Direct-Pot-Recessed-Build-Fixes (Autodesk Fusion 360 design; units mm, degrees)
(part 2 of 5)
sketch "Spring-side loaded retained M4 nut" plane through (0, 0, 37.9) normal (0, 0, 1) x axis (1, 0, 0)
  line L1 (14.1362, -51.3) -> (16.2724, -55)
  line L2 (9.8638, -51.3) -> (14.1362, -51.3)
  line L3 (7.7276, -55) -> (9.8638, -51.3)
  line L4 (9.8638, -58.7) -> (7.7276, -55)
  line L5 (14.1362, -58.7) -> (9.8638, -58.7)
  line L6 (16.2724, -55) -> (14.1362, -58.7)
extrude "Extrude7" cut sketch "Spring-side loaded retained M4 nut" along normal blind 3.5
work_plane "WorkPlane8" AlongDistance 37.9 ExtraOffset 0
sketch "Spring cup guide bolts" plane through (0, 0, 37.9) normal (0, 0, 1) x axis (1, 0, 0)
  circle C1 centre (5, -55) radius 1.7
extrude "Extrude8" cut sketch "Spring cup guide bolts" along normal blind 14.2
work_plane "WorkPlane9" AlongDistance 37.9 ExtraOffset 0
sketch "Spring cup guide bolts (1)" plane through (0, 0, 37.9) normal (0, 0, 1) x axis (1, 0, 0)
  circle C1 centre (19, -55) radius 1.7
extrude "Extrude9" cut sketch "Spring cup guide bolts (1)" along normal blind 14.2
work_plane "WorkPlane11" AlongDistance -18 ExtraOffset 0
sketch "Dedicated thick stop lug" plane through (-18, 0, 0) normal (1, 0, 0) x axis (0, 0, -1)
  line L1 (-72, 5) -> (-72, -5)
  line L2 (-95, 5) -> (-72, 5)
  line L3 (-95, -5) -> (-95, 5)
  line L4 (-72, -5) -> (-95, -5)
extrude "Extrude11" add sketch "Dedicated thick stop lug" along normal blind 11.5
work_plane "WorkPlane12" AlongDistance -18 ExtraOffset 0
sketch "Rounded stop contact" plane through (-18, 0, 0) normal (1, 0, 0) x axis (0, 0, -1)
  circle C1 centre (-95, 0) radius 5
extrude "Extrude12" add sketch "Rounded stop contact" along normal blind 11.5
work_plane "WorkPlane10" AlongDistance -36 ExtraOffset 0
sketch "Broad stop support ear" plane through (-36, 0, 0) normal (1, 0, 0) x axis (0, 0, -1)
  line L1 (-60, -20) -> (-60, -44)
  line L2 (-90, -20) -> (-60, -20)
  line L3 (-90, -44) -> (-90, -20)
  line L4 (-60, -44) -> (-90, -44)
extrude "Extrude10" add sketch "Broad stop support ear" along normal blind 12
work_plane "WorkPlane11" AlongDistance -24 ExtraOffset 0
sketch "Integrated steel-core end stop" plane through (-24, 0, 0) normal (1, 0, 0) x axis (0, 0, -1)
  circle C1 centre (-79.6754, -33.9652) radius 6
extrude "Extrude11" add sketch "Integrated steel-core end stop" along normal blind 15
work_plane "WorkPlane12" AlongDistance -36.1 ExtraOffset 0
sketch "M5 stop reinforcement bolt" plane through (-36.1, 0, 0) normal (1, 0, 0) x axis (0, 0, -1)
  circle C1 centre (-79.6754, -33.9652) radius 2.7
extrude "Extrude12" cut sketch "M5 stop reinforcement bolt" along normal blind 27.2
work_plane "WorkPlane13" AlongDistance -15.4 ExtraOffset 0
sketch "M5 captive stop nut" plane through (-15.4, 0, 0) normal (1, 0, 0) x axis (0, 0, -1)
  line L1 (-83.8754, -31.5403) -> (-79.6754, -29.1154)
  line L2 (-83.8754, -36.39) -> (-83.8754, -31.5403)
  line L3 (-79.6754, -38.8149) -> (-83.8754, -36.39)
  line L4 (-75.4754, -36.39) -> (-79.6754, -38.8149)
  line L5 (-75.4754, -31.5403) -> (-75.4754, -36.39)
  line L6 (-79.6754, -29.1154) -> (-75.4754, -31.5403)
extrude "Extrude13" cut sketch "M5 captive stop nut" along normal blind 6.5
work_plane "WorkPlane14" AlongDistance -36 ExtraOffset 0
sketch "Broad stop support ear (1)" plane through (-36, 0, 0) normal (1, 0, 0) x axis (0, 0, -1)
  line L1 (-60, 44) -> (-60, 20)
  line L2 (-90, 44) -> (-60, 44)
  line L3 (-90, 20) -> (-90, 44)
  line L4 (-60, 20) -> (-90, 20)
extrude "Extrude14" add sketch "Broad stop support ear (1)" along normal blind 12
work_plane "WorkPlane15" AlongDistance -24 ExtraOffset 0
sketch "Integrated steel-core end stop (1)" plane through (-24, 0, 0) normal (1, 0, 0) x axis (0, 0, -1)
  circle C1 centre (-79.6754, 33.9652) radius 6
extrude "Extrude15" add sketch "Integrated steel-core end stop (1)" along normal blind 15
work_plane "WorkPlane16" AlongDistance -36.1 ExtraOffset 0
sketch "M5 stop reinforcement bolt (1)" plane through (-36.1, 0, 0) normal (1, 0, 0) x axis (0, 0, -1)
  circle C1 centre (-79.6754, 33.9652) radius 2.7
extrude "Extrude16" cut sketch "M5 stop reinforcement bolt (1)" along normal blind 27.2
work_plane "WorkPlane17" AlongDistance -15.4 ExtraOffset 0
sketch "M5 captive stop nut (1)" plane through (-15.4, 0, 0) normal (1, 0, 0) x axis (0, 0, -1)
  line L1 (-83.8754, 36.39) -> (-79.6754, 38.8149)
  line L2 (-83.8754, 31.5403) -> (-83.8754, 36.39)
  line L3 (-79.6754, 29.1154) -> (-83.8754, 31.5403)
  line L4 (-75.4754, 31.5403) -> (-79.6754, 29.1154)
  line L5 (-75.4754, 36.39) -> (-75.4754, 31.5403)
  line L6 (-79.6754, 38.8149) -> (-75.4754, 36.39)
extrude "Extrude17" cut sketch "M5 captive stop nut (1)" along normal blind 6.5
work_plane "WorkPlane13" AlongDistance -24 ExtraOffset 0
sketch "Restore shaft socket through stop-lug root" plane through (-24, 0, 0) normal (1, 0, 0) x axis (0, 0, -1)
  line L1 (-69.6247, 6.65) -> (-60.3753, 6.65)
  arc A1 centre (-65, 0) radius 8.1 clockwise from (-60.3753, 6.65) to (-69.6247, 6.65)
extrude "Extrude13" cut sketch "Restore shaft socket through stop-lug root" along normal blind 48
work_plane "WorkPlane10" AlongDistance -24.1 ExtraOffset 0
sketch "Cam sweep clearance through crossblock" plane through (-24.1, 0, 0) normal (1, 0, 0) x axis (0, 0, -1)
  circle C1 centre (-65, 0) radius 51
extrude "Extrude10" cut sketch "Cam sweep clearance through crossblock" along normal blind 48.2
work_plane "WorkPlane10" AlongDistance 36 ExtraOffset 0
sketch "Rigid sensor carriage support" plane through (36, 0, 0) normal (1, 0, 0) x axis (0, 0, -1)
  line L1 (-49, -18) -> (-49, -28)
  line L2 (-81, -18) -> (-49, -18)
  line L3 (-81, -28) -> (-81, -18)
  line L4 (-49, -28) -> (-81, -28)
extrude "Extrude10" add sketch "Rigid sensor carriage support" along normal blind 44
work_plane "WorkPlane11" AlongDistance -28.1 ExtraOffset 0
sketch "M3 sensor carriage heat set" plane through (0, -28.1, 0) normal (0, 1, 0) x axis (1, 0, 0)
  circle C1 centre (74, -65) radius 2
extrude "Extrude11" cut sketch "M3 sensor carriage heat set" along normal blind 6.8
work_plane "WorkPlane12" AlongDistance 36 ExtraOffset 0
sketch "Rigid sensor carriage support (1)" plane through (36, 0, 0) normal (1, 0, 0) x axis (0, 0, -1)
  line L1 (-49, 28) -> (-49, 18)
  line L2 (-81, 28) -> (-49, 28)
  line L3 (-81, 18) -> (-81, 28)
  line L4 (-49, 18) -> (-81, 18)
extrude "Extrude12" add sketch "Rigid sensor carriage support (1)" along normal blind 44
work_plane "WorkPlane13" AlongDistance 21.3 ExtraOffset 0
sketch "M3 sensor carriage heat set (1)" plane through (0, 21.3, 0) normal (0, 1, 0) x axis (1, 0, 0)
  circle C1 centre (74, -65) radius 2
extrude "Extrude13" cut sketch "M3 sensor carriage heat set (1)" along normal blind 6.8
work_plane "WorkPlane1" AlongDistance -24 ExtraOffset 0
sketch "Controlled follower end float" plane through (-24, 0, 0) normal (1, 0, 0) x axis (0, 0, -1)
  circle C1 centre (-12, -35) radius 6
extrude "Extrude1" new body sketch "Controlled follower end float" along normal blind 27.8 bodies "P21 Follower left axial spacer"
work_plane "WorkPlane2" AlongDistance -24.1 ExtraOffset 0
sketch "Pivot sleeve running clearance" plane through (-24.1, 0, 0) normal (1, 0, 0) x axis (0, 0, -1)
  circle C1 centre (-12, -35) radius 4.2
extrude "Extrude2" cut sketch "Pivot sleeve running clearance" along normal blind 28
work_plane "WorkPlane1" AlongDistance 20.2 ExtraOffset 0
sketch "Controlled follower end float" plane through (20.2, 0, 0) normal (1, 0, 0) x axis (0, 0, -1)
  circle C1 centre (-12, -35) radius 6
extrude "Extrude1" new body sketch "Controlled follower end float" along normal blind 3.8 bodies "P22 Follower right axial spacer"
work_plane "WorkPlane2" AlongDistance 20.1 ExtraOffset 0
sketch "Pivot sleeve running clearance" plane through (20.1, 0, 0) normal (1, 0, 0) x axis (0, 0, -1)
  circle C1 centre (-12, -35) radius 4.2
extrude "Extrude2" cut sketch "Pivot sleeve running clearance" along normal blind 4
work_plane "WorkPlane1" AlongDistance 3.1 ExtraOffset 0
sketch "Roller axle M3 nut" plane through (3.1, 0, 0) normal (1, 0, 0) x axis (0, 0, -1)
  line L1 (-14.75, 1.5877) -> (-12, 3.1754)
  line L2 (-14.75, -1.5877) -> (-14.75, 1.5877)
  line L3 (-12, -3.1754) -> (-14.75, -1.5877)
  line L4 (-9.25, -1.5877) -> (-12, -3.1754)
  line L5 (-9.25, 1.5877) -> (-9.25, -1.5877)
  line L6 (-12, 3.1754) -> (-9.25, 1.5877)
extrude "Extrude1" new body sketch "Roller axle M3 nut" along normal blind 2.4 bodies "HARDWARE Roller axle M3 nut"
work_plane "WorkPlane2" AlongDistance 3 ExtraOffset 0
sketch "Thread envelope" plane through (3, 0, 0) normal (1, 0, 0) x axis (0, 0, -1)
  circle C1 centre (-12, 0) radius 1.5
extrude "Extrude2" cut sketch "Thread envelope" along normal blind 2.6
work_plane "WorkPlane14" AlongDistance 23.9 ExtraOffset 0
sketch "Cam lateral service opening" plane through (23.9, 0, 0) normal (1, 0, 0) x axis (0, 0, -1)
  line L1 (-42.2047, 46.7373) -> (-43.8497, 47.5044)
  line L2 (-40.5875, 45.9133) -> (-42.2047, 46.7373)
  line L3 (-39, 45.0333) -> (-40.5875, 45.9133)
  line L4 (-37.4442, 44.0985) -> (-39, 45.0333)
  line L5 (-35.922, 43.11) -> (-37.4442, 44.0985)
  line L6 (-34.4352, 42.0689) -> (-35.922, 43.11)
  line L7 (-32.9856, 40.9766) -> (-34.4352, 42.0689)
  line L8 (-31.575, 39.8343) -> (-32.9856, 40.9766)
  line L9 (-30.2052, 38.6435) -> (-31.575, 39.8343)
  line L10 (-28.8778, 37.4057) -> (-30.2052, 38.6435)
  line L11 (-27.5943, 36.1222) -> (-28.8778, 37.4057)
  line L12 (-26.3565, 34.7948) -> (-27.5943, 36.1222)
  line L13 (-25.1657, 33.425) -> (-26.3565, 34.7948)
  line L14 (-24.0234, 32.0144) -> (-25.1657, 33.425)
  line L15 (-22.9311, 30.5648) -> (-24.0234, 32.0144)
  line L16 (-21.89, 29.078) -> (-22.9311, 30.5648)
  line L17 (-20.9015, 27.5558) -> (-21.89, 29.078)
  line L18 (-19.9667, 26) -> (-20.9015, 27.5558)
  line L19 (-19.0867, 24.4125) -> (-19.9667, 26)
  line L20 (-18.2627, 22.7953) -> (-19.0867, 24.4125)
  line L21 (-17.4956, 21.1503) -> (-18.2627, 22.7953)
  line L22 (-16.7864, 19.4795) -> (-17.4956, 21.1503)
  line L23 (-16.136, 17.785) -> (-16.7864, 19.4795)
  line L24 (-15.5451, 16.0689) -> (-16.136, 17.785)
  line L25 (-15.0144, 14.3331) -> (-15.5451, 16.0689)
  line L26 (-14.5446, 12.5799) -> (-15.0144, 14.3331)
  line L27 (-14.1363, 10.8114) -> (-14.5446, 12.5799)
  line L28 (-13.79, 9.0297) -> (-14.1363, 10.8114)
  line L29 (-13.5061, 7.237) -> (-13.79, 9.0297)
  line L30 (-13.2849, 5.4355) -> (-13.5061, 7.237)
  line L31 (-13.1267, 3.6273) -> (-13.2849, 5.4355)
  line L32 (-13.0317, 1.8148) -> (-13.1267, 3.6273)
  line L33 (-13, 0) -> (-13.0317, 1.8148)
  line L34 (-13.0317, -1.8148) -> (-13, 0)
  line L35 (-13.1267, -3.6273) -> (-13.0317, -1.8148)
  line L36 (-13.2849, -5.4355) -> (-13.1267, -3.6273)
  line L37 (-13.5061, -7.237) -> (-13.2849, -5.4355)
  line L38 (-13.79, -9.0297) -> (-13.5061, -7.237)
  line L39 (-14.1363, -10.8114) -> (-13.79, -9.0297)
  line L40 (-14.5446, -12.5799) -> (-14.1363, -10.8114)
  line L41 (-15.0144, -14.3331) -> (-14.5446, -12.5799)
  line L42 (-15.5451, -16.0689) -> (-15.0144, -14.3331)
  line L43 (-16.136, -17.785) -> (-15.5451, -16.0689)
  line L44 (-16.7864, -19.4795) -> (-16.136, -17.785)
  line L45 (-17.4956, -21.1503) -> (-16.7864, -19.4795)
  line L46 (-18.2627, -22.7953) -> (-17.4956, -21.1503)
  line L47 (-19.0867, -24.4125) -> (-18.2627, -22.7953)
  line L48 (-19.9667, -26) -> (-19.0867, -24.4125)
  line L49 (-20.9015, -27.5558) -> (-19.9667, -26)
  line L50 (-21.89, -29.078) -> (-20.9015, -27.5558)
  line L51 (-22.9311, -30.5648) -> (-21.89, -29.078)
  line L52 (-24.0234, -32.0144) -> (-22.9311, -30.5648)
  line L53 (-25.1657, -33.425) -> (-24.0234, -32.0144)
  line L54 (-26.3565, -34.7948) -> (-25.1657, -33.425)
  line L55 (-27.5943, -36.1222) -> (-26.3565, -34.7948)
  line L56 (-28.8778, -37.4057) -> (-27.5943, -36.1222)
  line L57 (-30.2052, -38.6435) -> (-28.8778, -37.4057)
  line L58 (-31.575, -39.8343) -> (-30.2052, -38.6435)
  line L59 (-32.9856, -40.9766) -> (-31.575, -39.8343)
  line L60 (-34.4352, -42.0689) -> (-32.9856, -40.9766)
  line L61 (-35.922, -43.11) -> (-34.4352, -42.0689)
  line L62 (-37.4442, -44.0985) -> (-35.922, -43.11)
  line L63 (-39, -45.0333) -> (-37.4442, -44.0985)
  line L64 (-40.5875, -45.9133) -> (-39, -45.0333)
  line L65 (-42.2047, -46.7373) -> (-40.5875, -45.9133)
  line L66 (-43.8497, -47.5044) -> (-42.2047, -46.7373)
  line L67 (-54.4248, -23.7522) -> (-43.8497, -47.5044)
  line L68 (-53.6024, -23.3686) -> (-54.4248, -23.7522)
  line L69 (-52.7937, -22.9566) -> (-53.6024, -23.3686)
  line L70 (-52, -22.5167) -> (-52.7937, -22.9566)
  line L71 (-51.2221, -22.0493) -> (-52, -22.5167)
  line L72 (-50.461, -21.555) -> (-51.2221, -22.0493)
  line L73 (-49.7176, -21.0344) -> (-50.461, -21.555)
  line L74 (-48.9928, -20.4883) -> (-49.7176, -21.0344)
  line L75 (-48.2875, -19.9172) -> (-48.9928, -20.4883)
  line L76 (-47.6026, -19.3218) -> (-48.2875, -19.9172)
  line L77 (-46.9389, -18.7028) -> (-47.6026, -19.3218)
  line L78 (-46.2972, -18.0611) -> (-46.9389, -18.7028)
  line L79 (-45.6782, -17.3974) -> (-46.2972, -18.0611)
  line L80 (-45.0828, -16.7125) -> (-45.6782, -17.3974)
  line L81 (-44.5117, -16.0072) -> (-45.0828, -16.7125)
  line L82 (-43.9656, -15.2824) -> (-44.5117, -16.0072)
  line L83 (-43.445, -14.539) -> (-43.9656, -15.2824)
  line L84 (-42.9507, -13.7779) -> (-43.445, -14.539)
  line L85 (-42.4833, -13) -> (-42.9507, -13.7779)
  line L86 (-42.0434, -12.2063) -> (-42.4833, -13)
  line L87 (-41.6314, -11.3976) -> (-42.0434, -12.2063)
  line L88 (-41.2478, -10.5752) -> (-41.6314, -11.3976)
  line L89 (-40.8932, -9.7398) -> (-41.2478, -10.5752)
  line L90 (-40.568, -8.8925) -> (-40.8932, -9.7398)
  line L91 (-40.2725, -8.0344) -> (-40.568, -8.8925)
  line L92 (-40.0072, -7.1666) -> (-40.2725, -8.0344)
  line L93 (-39.7723, -6.29) -> (-40.0072, -7.1666)
  line L94 (-39.5682, -5.4057) -> (-39.7723, -6.29)
  line L95 (-39.395, -4.5149) -> (-39.5682, -5.4057)
  line L96 (-39.253, -3.6185) -> (-39.395, -4.5149)
  line L97 (-39.1424, -2.7177) -> (-39.253, -3.6185)
  line L98 (-39.0633, -1.8137) -> (-39.1424, -2.7177)
  line L99 (-39.0158, -0.9074) -> (-39.0633, -1.8137)
  line L100 (-39, 0) -> (-39.0158, -0.9074)
  line L101 (-39.0158, 0.9074) -> (-39, 0)
  line L102 (-39.0633, 1.8137) -> (-39.0158, 0.9074)
  line L103 (-39.1424, 2.7177) -> (-39.0633, 1.8137)
  line L104 (-39.253, 3.6185) -> (-39.1424, 2.7177)
  line L105 (-39.395, 4.5149) -> (-39.253, 3.6185)
  line L106 (-39.5682, 5.4057) -> (-39.395, 4.5149)
  line L107 (-39.7723, 6.29) -> (-39.5682, 5.4057)
  line L108 (-40.0072, 7.1666) -> (-39.7723, 6.29)
  line L109 (-40.2725, 8.0344) -> (-40.0072, 7.1666)
  line L110 (-40.568, 8.8925) -> (-40.2725, 8.0344)
  line L111 (-40.8932, 9.7398) -> (-40.568, 8.8925)
  line L112 (-41.2478, 10.5752) -> (-40.8932, 9.7398)
  line L113 (-41.6314, 11.3976) -> (-41.2478, 10.5752)
  line L114 (-42.0434, 12.2063) -> (-41.6314, 11.3976)
  line L115 (-42.4833, 13) -> (-42.0434, 12.2063)
  line L116 (-42.9507, 13.7779) -> (-42.4833, 13)
  line L117 (-43.445, 14.539) -> (-42.9507, 13.7779)
  line L118 (-43.9656, 15.2824) -> (-43.445, 14.539)
  line L119 (-44.5117, 16.0072) -> (-43.9656, 15.2824)
  line L120 (-45.0828, 16.7125) -> (-44.5117, 16.0072)
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extrude "Extrude14" cut sketch "Cam lateral service opening" along normal blind 12.2
work_plane "WorkPlane15" AlongDistance 36 ExtraOffset 0
sketch "Clear service path beneath sensor rails" plane through (36, 0, 0) normal (1, 0, 0) x axis (0, 0, -1)
  line L1 (-48.9, -18) -> (-48.9, -28)
  line L2 (-56, -18) -> (-48.9, -18)
  line L3 (-56, -28) -> (-56, -18)
  line L4 (-48.9, -28) -> (-56, -28)
extrude "Extrude15" cut sketch "Clear service path beneath sensor rails" along normal blind 44.1
work_plane "WorkPlane16" AlongDistance 36 ExtraOffset 0
sketch "Clear service path beneath sensor rails (1)" plane through (36, 0, 0) normal (1, 0, 0) x axis (0, 0, -1)
  line L1 (-48.9, 28) -> (-48.9, 18)
  line L2 (-56, 28) -> (-48.9, 28)
  line L3 (-56, 18) -> (-56, 28)
  line L4 (-48.9, 18) -> (-56, 18)
extrude "Extrude16" cut sketch "Clear service path beneath sensor rails (1)" along normal blind 44.1
work_plane "WorkPlane11" AlongDistance -24 ExtraOffset 0
sketch "Raise mount clear of rail bolt axes" plane through (-24, 0, 0) normal (1, 0, 0) x axis (0, 0, -1)
  line L1 (-52, -44) -> (-52, -66)
  line L2 (-57, -44) -> (-52, -44)
  line L3 (-57, -66) -> (-57, -44)
  line L4 (-52, -66) -> (-57, -66)
extrude "Extrude11" add sketch "Raise mount clear of rail bolt axes" along normal blind 48
work_plane "WorkPlane12" AlongDistance -24 ExtraOffset 0
sketch "Close old block mounting hole" plane through (-24, 0, 0) normal (1, 0, 0) x axis (0, 0, -1)
  circle C1 centre (-44, -59) radius 2.01
extrude "Extrude12" add sketch "Close old block mounting hole" along normal blind 8.7
work_plane "WorkPlane13" AlongDistance -24.1 ExtraOffset 0
sketch "Raised M3 block insert" plane through (-24.1, 0, 0) normal (1, 0, 0) x axis (0, 0, -1)
  circle C1 centre (-52, -59) radius 2
extrude "Extrude13" cut sketch "Raised M3 block insert" along normal blind 8.9
work_plane "WorkPlane14" AlongDistance 15.3 ExtraOffset 0
sketch "Close old block mounting hole (1)" plane through (15.3, 0, 0) normal (1, 0, 0) x axis (0, 0, -1)
  circle C1 centre (-44, -59) radius 2.01
extrude "Extrude14" add sketch "Close old block mounting hole (1)" along normal blind 8.7
work_plane "WorkPlane15" AlongDistance 15.2 ExtraOffset 0
sketch "Raised M3 block insert (1)" plane through (15.2, 0, 0) normal (1, 0, 0) x axis (0, 0, -1)
  circle C1 centre (-52, -59) radius 2
extrude "Extrude15" cut sketch "Raised M3 block insert (1)" along normal blind 8.9
work_plane "WorkPlane18" AlongDistance -36 ExtraOffset 0
sketch "Close old plate mounting hole" plane through (-36, 0, 0) normal (1, 0, 0) x axis (0, 0, -1)
  circle C1 centre (-44, -59) radius 1.71
extrude "Extrude18" add sketch "Close old plate mounting hole" along normal blind 12
work_plane "WorkPlane19" AlongDistance -36.1 ExtraOffset 0
sketch "Raised M3 block fastener" plane through (-36.1, 0, 0) normal (1, 0, 0) x axis (0, 0, -1)
  circle C1 centre (-52, -59) radius 1.7
extrude "Extrude19" cut sketch "Raised M3 block fastener" along normal blind 12.2
work_plane "WorkPlane17" AlongDistance 24 ExtraOffset 0
sketch "Close old plate mounting hole" plane through (24, 0, 0) normal (1, 0, 0) x axis (0, 0, -1)
  circle C1 centre (-44, -59) radius 1.71
extrude "Extrude17" add sketch "Close old plate mounting hole" along normal blind 12
work_plane "WorkPlane18" AlongDistance 23.9 ExtraOffset 0
sketch "Raised M3 block fastener" plane through (23.9, 0, 0) normal (1, 0, 0) x axis (0, 0, -1)
  circle C1 centre (-52, -59) radius 1.7
extrude "Extrude18" cut sketch "Raised M3 block fastener" along normal blind 12.2
work_plane "WorkPlane16" AlongDistance -24 ExtraOffset 0
sketch "Close old block mounting hole (2)" plane through (-24, 0, 0) normal (1, 0, 0) x axis (0, 0, -1)
  circle C1 centre (-44, -51) radius 2.01
extrude "Extrude16" add sketch "Close old block mounting hole (2)" along normal blind 8.7
work_plane "WorkPlane17" AlongDistance -24.1 ExtraOffset 0
sketch "Raised M3 block insert (2)" plane through (-24.1, 0, 0) normal (1, 0, 0) x axis (0, 0, -1)
  circle C1 centre (-52, -51) radius 2
extrude "Extrude17" cut sketch "Raised M3 block insert (2)" along normal blind 8.9
work_plane "WorkPlane18" AlongDistance 15.3 ExtraOffset 0
sketch "Close old block mounting hole (3)" plane through (15.3, 0, 0) normal (1, 0, 0) x axis (0, 0, -1)
  circle C1 centre (-44, -51) radius 2.01
extrude "Extrude18" add sketch "Close old block mounting hole (3)" along normal blind 8.7
work_plane "WorkPlane19" AlongDistance 15.2 ExtraOffset 0
sketch "Raised M3 block insert (3)" plane through (15.2, 0, 0) normal (1, 0, 0) x axis (0, 0, -1)
  circle C1 centre (-52, -51) radius 2
extrude "Extrude19" cut sketch "Raised M3 block insert (3)" along normal blind 8.9
work_plane "WorkPlane20" AlongDistance -36 ExtraOffset 0
sketch "Close old plate mounting hole (1)" plane through (-36, 0, 0) normal (1, 0, 0) x axis (0, 0, -1)
  circle C1 centre (-44, -51) radius 1.71
extrude "Extrude20" add sketch "Close old plate mounting hole (1)" along normal blind 12
work_plane "WorkPlane21" AlongDistance -36.1 ExtraOffset 0
sketch "Raised M3 block fastener (1)" plane through (-36.1, 0, 0) normal (1, 0, 0) x axis (0, 0, -1)
  circle C1 centre (-52, -51) radius 1.7
extrude "Extrude21" cut sketch "Raised M3 block fastener (1)" along normal blind 12.2
work_plane "WorkPlane19" AlongDistance 24 ExtraOffset 0
sketch "Close old plate mounting hole (1)" plane through (24, 0, 0) normal (1, 0, 0) x axis (0, 0, -1)
  circle C1 centre (-44, -51) radius 1.71
extrude "Extrude19" add sketch "Close old plate mounting hole (1)" along normal blind 12
work_plane "WorkPlane20" AlongDistance 23.9 ExtraOffset 0
sketch "Raised M3 block fastener (1)" plane through (23.9, 0, 0) normal (1, 0, 0) x axis (0, 0, -1)
  circle C1 centre (-52, -51) radius 1.7
extrude "Extrude20" cut sketch "Raised M3 block fastener (1)" along normal blind 12.2
work_plane "WorkPlane20" AlongDistance 51.9 ExtraOffset 0
sketch "Continue adjuster bore" plane through (0, 0, 51.9) normal (0, 0, 1) x axis (1, 0, 0)
  circle C1 centre (12, -55) radius 2.2
extrude "Extrude20" cut sketch "Continue adjuster bore" along normal blind 5.2
work_plane "WorkPlane21" AlongDistance 51.9 ExtraOffset 0
sketch "Continue guide bore" plane through (0, 0, 51.9) normal (0, 0, 1) x axis (1, 0, 0)
  circle C1 centre (5, -55) radius 1.7
extrude "Extrude21" cut sketch "Continue guide bore" along normal blind 5.2
work_plane "WorkPlane22" AlongDistance 51.9 ExtraOffset 0
sketch "Continue guide bore (1)" plane through (0, 0, 51.9) normal (0, 0, 1) x axis (1, 0, 0)
  circle C1 centre (19, -55) radius 1.7
extrude "Extrude22" cut sketch "Continue guide bore (1)" along normal blind 5.2
work_plane "WorkPlane23" AlongDistance -24.1 ExtraOffset 0
sketch "Preserve cam sweep clearance" plane through (-24.1, 0, 0) normal (1, 0, 0) x axis (0, 0, -1)
  circle C1 centre (-65, 0) radius 51
extrude "Extrude23" cut sketch "Preserve cam sweep clearance" along normal blind 48.2
work_plane "WorkPlane8" AlongDistance 37.25 ExtraOffset 0
sketch "Flat shoulder aligns with shaft print bed" plane through (37.25, 0, 0) normal (1, 0, 0) x axis (0, 0, -1)
  line L1 (-54, 11) -> (-54, 6.5)
  line L2 (-76, 11) -> (-54, 11)
  line L3 (-76, 6.5) -> (-76, 11)
  line L4 (-54, 6.5) -> (-76, 6.5)
extrude "Extrude8" cut sketch "Flat shoulder aligns with shaft print bed" along normal blind 3.2
work_plane "WorkPlane1" AlongDistance -23.85 ExtraOffset 0
sketch "Controlled rotor axial clearance" plane through (-23.85, 0, 0) normal (1, 0, 0) x axis (0, 0, -1)
  circle C1 centre (-65, 0) radius 10
extrude "Extrude1" new body sketch "Controlled rotor axial clearance" along normal blind 16.85 bodies "P23 Left rotor thrust spacer"
work_plane "WorkPlane2" AlongDistance -23.95 ExtraOffset 0
sketch "Free spacer bore" plane through (-23.95, 0, 0) normal (1, 0, 0) x axis (0, 0, -1)
  circle C1 centre (-65, 0) radius 8.2
extrude "Extrude2" cut sketch "Free spacer bore" along normal blind 17.05
work_plane "WorkPlane1" AlongDistance 7 ExtraOffset 0
sketch "Controlled rotor axial clearance" plane through (7, 0, 0) normal (1, 0, 0) x axis (0, 0, -1)
  circle C1 centre (-65, 0) radius 10
extrude "Extrude1" new body sketch "Controlled rotor axial clearance" along normal blind 16.85 bodies "P24 Right rotor thrust spacer"
work_plane "WorkPlane2" AlongDistance 6.9 ExtraOffset 0
sketch "Free spacer bore" plane through (6.9, 0, 0) normal (1, 0, 0) x axis (0, 0, -1)
  circle C1 centre (-65, 0) radius 8.2
extrude "Extrude2" cut sketch "Free spacer bore" along normal blind 17.05
work_plane "WorkPlane22" AlongDistance -76 ExtraOffset 0
sketch "Restore rail bolt clearance after hole filling" plane through (0, -76, 0) normal (0, 1, 0) x axis (1, 0, 0)
  circle C1 centre (-30, -45) radius 2.7
extrude "Extrude22" cut sketch "Restore rail bolt clearance after hole filling" along normal blind 22
work_plane "WorkPlane23" AlongDistance 54 ExtraOffset 0
sketch "Restore rail bolt clearance after hole filling (1)" plane through (0, 54, 0) normal (0, 1, 0) x axis (1, 0, 0)
  circle C1 centre (-30, -45) radius 2.7
work_plane "WorkPlane24" AlongDistance -55 ExtraOffset 0
sketch "Restore rail head access after hole filling" plane through (0, -55, 0) normal (0, 1, 0) x axis (1, 0, 0)
  circle C1 centre (-30, -45) radius 5.3
extrude "Extrude24" cut sketch "Restore rail head access after hole filling" along normal blind 12
work_plane "WorkPlane25" AlongDistance 43 ExtraOffset 0
sketch "Restore rail head access after hole filling (1)" plane through (0, 43, 0) normal (0, 1, 0) x axis (1, 0, 0)
  circle C1 centre (-30, -45) radius 5.3
work_plane "WorkPlane21" AlongDistance -76 ExtraOffset 0
sketch "Restore rail bolt clearance after hole filling" plane through (0, -76, 0) normal (0, 1, 0) x axis (1, 0, 0)
  circle C1 centre (30, -45) radius 2.7
extrude "Extrude21" cut sketch "Restore rail bolt clearance after hole filling" along normal blind 22
work_plane "WorkPlane22" AlongDistance 54 ExtraOffset 0
sketch "Restore rail bolt clearance after hole filling (1)" plane through (0, 54, 0) normal (0, 1, 0) x axis (1, 0, 0)
  circle C1 centre (30, -45) radius 2.7
work_plane "WorkPlane23" AlongDistance -55 ExtraOffset 0
sketch "Restore rail head access after hole filling" plane through (0, -55, 0) normal (0, 1, 0) x axis (1, 0, 0)
  circle C1 centre (30, -45) radius 5.3
extrude "Extrude23" cut sketch "Restore rail head access after hole filling" along normal blind 12
work_plane "WorkPlane24" AlongDistance 43 ExtraOffset 0
sketch "Restore rail head access after hole filling (1)" plane through (0, 43, 0) normal (0, 1, 0) x axis (1, 0, 0)
  circle C1 centre (30, -45) radius 5.3
work_plane "WorkPlane14" AlongDistance -18.1 ExtraOffset 0
sketch "Stop lug clearance for concentric thrust spacer" plane through (-18.1, 0, 0) normal (1, 0, 0) x axis (0, 0, -1)
  circle C1 centre (-65, 0) radius 10.2
extrude "Extrude14" cut sketch "Stop lug clearance for concentric thrust spacer" along normal blind 11
work_plane "WorkPlane15" AlongDistance -18.1 ExtraOffset 0
sketch "Complete stop lug relief to rotor face" plane through (-18.1, 0, 0) normal (1, 0, 0) x axis (0, 0, -1)
  circle C1 centre (-65, 0) radius 10.2
extrude "Extrude15" cut sketch "Complete stop lug relief to rotor face" along normal blind 11.1
ground "Pin2"
ground "Pin3"
ground "Pin4"
ground "Pin5"
ground "Pin6"
ground "Pin11"
ground "Pin12"
ground "Pin48"
ground "Pin49"
work_plane "WorkPlane24" AlongDistance -24 ExtraOffset 0
sketch "Extra roof over relocated heat-set inserts" plane through (-24, 0, 0) normal (1, 0, 0) x axis (0, 0, -1)
  line L1 (-57, -44) -> (-57, -66)
  line L2 (-59, -44) -> (-57, -44)
  line L3 (-59, -66) -> (-59, -44)
  line L4 (-57, -66) -> (-59, -66)
extrude "Extrude24" add sketch "Extra roof over relocated heat-set inserts" along normal blind 48
work_plane "WorkPlane25" AlongDistance -24 ExtraOffset 0
sketch "Fill former insert location" plane through (-24, 0, 0) normal (1, 0, 0) x axis (0, 0, -1)
  circle C1 centre (-52, -59) radius 2.01
extrude "Extrude25" add sketch "Fill former insert location" along normal blind 8.7
work_plane "WorkPlane26" AlongDistance 15.3 ExtraOffset 0
sketch "Fill former insert location (1)" plane through (15.3, 0, 0) normal (1, 0, 0) x axis (0, 0, -1)
  circle C1 centre (-52, -59) radius 2.01
extrude "Extrude26" add sketch "Fill former insert location (1)" along normal blind 8.7
work_plane "WorkPlane26" AlongDistance -36 ExtraOffset 0
sketch "Fill former plate mounting hole" plane through (-36, 0, 0) normal (1, 0, 0) x axis (0, 0, -1)
  circle C1 centre (-52, -59) radius 1.71
extrude "Extrude26" add sketch "Fill former plate mounting hole" along normal blind 12
work_plane "WorkPlane25" AlongDistance 24 ExtraOffset 0
sketch "Fill former plate mounting hole" plane through (24, 0, 0) normal (1, 0, 0) x axis (0, 0, -1)
  circle C1 centre (-52, -59) radius 1.71
extrude "Extrude25" add sketch "Fill former plate mounting hole" along normal blind 12
work_plane "WorkPlane27" AlongDistance -24 ExtraOffset 0
sketch "Fill former insert location (2)" plane through (-24, 0, 0) normal (1, 0, 0) x axis (0, 0, -1)
  circle C1 centre (-52, -51) radius 2.01
extrude "Extrude27" add sketch "Fill former insert location (2)" along normal blind 8.7
work_plane "WorkPlane28" AlongDistance 15.3 ExtraOffset 0
sketch "Fill former insert location (3)" plane through (15.3, 0, 0) normal (1, 0, 0) x axis (0, 0, -1)
  circle C1 centre (-52, -51) radius 2.01
extrude "Extrude28" add sketch "Fill former insert location (3)" along normal blind 8.7
work_plane "WorkPlane27" AlongDistance -36 ExtraOffset 0
sketch "Fill former plate mounting hole (1)" plane through (-36, 0, 0) normal (1, 0, 0) x axis (0, 0, -1)
  circle C1 centre (-52, -51) radius 1.71
extrude "Extrude27" add sketch "Fill former plate mounting hole (1)" along normal blind 12
work_plane "WorkPlane26" AlongDistance 24 ExtraOffset 0
sketch "Fill former plate mounting hole (1)" plane through (24, 0, 0) normal (1, 0, 0) x axis (0, 0, -1)
  circle C1 centre (-52, -51) radius 1.71
extrude "Extrude26" add sketch "Fill former plate mounting hole (1)" along normal blind 12
work_plane "WorkPlane29" AlongDistance -24.1 ExtraOffset 0
sketch "Relocated insert with cam-side retaining wall" plane through (-24.1, 0, 0) normal (1, 0, 0) x axis (0, 0, -1)
  circle C1 centre (-53.5, -62) radius 2
extrude "Extrude29" cut sketch "Relocated insert with cam-side retaining wall" along normal blind 8.9
work_plane "WorkPlane30" AlongDistance 15.3 ExtraOffset 0
sketch "Relocated insert with cam-side retaining wall (1)" plane through (15.3, 0, 0) normal (1, 0, 0) x axis (0, 0, -1)
  circle C1 centre (-53.5, -62) radius 2
extrude "Extrude30" cut sketch "Relocated insert with cam-side retaining wall (1)" along normal blind 8.9
work_plane "WorkPlane28" AlongDistance -36.1 ExtraOffset 0
sketch "Relocated mount above rail counterbore" plane through (-36.1, 0, 0) normal (1, 0, 0) x axis (0, 0, -1)
  circle C1 centre (-53.5, -62) radius 1.7
extrude "Extrude28" cut sketch "Relocated mount above rail counterbore" along normal blind 12.2
work_plane "WorkPlane27" AlongDistance 23.9 ExtraOffset 0
sketch "Relocated mount above rail counterbore" plane through (23.9, 0, 0) normal (1, 0, 0) x axis (0, 0, -1)
  circle C1 centre (-53.5, -62) radius 1.7
extrude "Extrude27" cut sketch "Relocated mount above rail counterbore" along normal blind 12.2
work_plane "WorkPlane31" AlongDistance -24.1 ExtraOffset 0
sketch "Relocated insert with cam-side retaining wall (2)" plane through (-24.1, 0, 0) normal (1, 0, 0) x axis (0, 0, -1)
  circle C1 centre (-53.5, -54) radius 2
extrude "Extrude31" cut sketch "Relocated insert with cam-side retaining wall (2)" along normal blind 8.9
work_plane "WorkPlane32" AlongDistance 15.3 ExtraOffset 0
sketch "Relocated insert with cam-side retaining wall (3)" plane through (15.3, 0, 0) normal (1, 0, 0) x axis (0, 0, -1)
  circle C1 centre (-53.5, -54) radius 2
extrude "Extrude32" cut sketch "Relocated insert with cam-side retaining wall (3)" along normal blind 8.9
work_plane "WorkPlane29" AlongDistance -36.1 ExtraOffset 0
sketch "Relocated mount above rail counterbore (1)" plane through (-36.1, 0, 0) normal (1, 0, 0) x axis (0, 0, -1)
  circle C1 centre (-53.5, -54) radius 1.7
extrude "Extrude29" cut sketch "Relocated mount above rail counterbore (1)" along normal blind 12.2
work_plane "WorkPlane28" AlongDistance 23.9 ExtraOffset 0
sketch "Relocated mount above rail counterbore (1)" plane through (23.9, 0, 0) normal (1, 0, 0) x axis (0, 0, -1)
  circle C1 centre (-53.5, -54) radius 1.7
extrude "Extrude28" cut sketch "Relocated mount above rail counterbore (1)" along normal blind 12.2
work_plane "WorkPlane33" AlongDistance 51.9 ExtraOffset 0
sketch "Continue adjuster bore through roof" plane through (0, 0, 51.9) normal (0, 0, 1) x axis (1, 0, 0)
  circle C1 centre (12, -55) radius 2.2
extrude "Extrude33" cut sketch "Continue adjuster bore through roof" along normal blind 7.2
work_plane "WorkPlane34" AlongDistance 51.9 ExtraOffset 0
sketch "Continue guide bore through roof" plane through (0, 0, 51.9) normal (0, 0, 1) x axis (1, 0, 0)
  circle C1 centre (5, -55) radius 1.7
extrude "Extrude34" cut sketch "Continue guide bore through roof" along normal blind 7.2
work_plane "WorkPlane35" AlongDistance 51.9 ExtraOffset 0
sketch "Continue guide bore through roof (1)" plane through (0, 0, 51.9) normal (0, 0, 1) x axis (1, 0, 0)
  circle C1 centre (19, -55) radius 1.7
extrude "Extrude35" cut sketch "Continue guide bore through roof (1)" along normal blind 7.2
work_plane "WorkPlane36" AlongDistance -24.1 ExtraOffset 0
sketch "Restore cam envelope after pocket repair" plane through (-24.1, 0, 0) normal (1, 0, 0) x axis (0, 0, -1)
  circle C1 centre (-65, 0) radius 51
extrude "Extrude36" cut sketch "Restore cam envelope after pocket repair" along normal blind 48.2
work_plane "WorkPlane30" AlongDistance -76 ExtraOffset 0
sketch "Preserve rail shank passage" plane through (0, -76, 0) normal (0, 1, 0) x axis (1, 0, 0)
  circle C1 centre (-30, -45) radius 2.7
work_plane "WorkPlane31" AlongDistance 54 ExtraOffset 0
sketch "Preserve rail shank passage (1)" plane through (0, 54, 0) normal (0, 1, 0) x axis (1, 0, 0)
  circle C1 centre (-30, -45) radius 2.7
work_plane "WorkPlane32" AlongDistance -55 ExtraOffset 0
sketch "Preserve rail head passage" plane through (0, -55, 0) normal (0, 1, 0) x axis (1, 0, 0)
  circle C1 centre (-30, -45) radius 5.3
extrude "Extrude32" cut sketch "Preserve rail head passage" along normal blind 12
work_plane "WorkPlane33" AlongDistance 43 ExtraOffset 0
sketch "Preserve rail head passage (1)" plane through (0, 43, 0) normal (0, 1, 0) x axis (1, 0, 0)
  circle C1 centre (-30, -45) radius 5.3
work_plane "WorkPlane29" AlongDistance -76 ExtraOffset 0
sketch "Preserve rail shank passage" plane through (0, -76, 0) normal (0, 1, 0) x axis (1, 0, 0)
  circle C1 centre (30, -45) radius 2.7
work_plane "WorkPlane30" AlongDistance 54 ExtraOffset 0
sketch "Preserve rail shank passage (1)" plane through (0, 54, 0) normal (0, 1, 0) x axis (1, 0, 0)
  circle C1 centre (30, -45) radius 2.7
work_plane "WorkPlane31" AlongDistance -55 ExtraOffset 0
sketch "Preserve rail head passage" plane through (0, -55, 0) normal (0, 1, 0) x axis (1, 0, 0)
  circle C1 centre (30, -45) radius 5.3
extrude "Extrude31" cut sketch "Preserve rail head passage" along normal blind 12
work_plane "WorkPlane32" AlongDistance 43 ExtraOffset 0
sketch "Preserve rail head passage (1)" plane through (0, 43, 0) normal (0, 1, 0) x axis (1, 0, 0)
  circle C1 centre (30, -45) radius 5.3
work_plane "WorkPlane16" AlongDistance -5 ExtraOffset 0
sketch "Flat washer seat for sensor-drive shaft clamp" plane through (-5, 0, 0) normal (1, 0, 0) x axis (0, 0, -1)
  line L1 (-60, 22) -> (-60, 20)
  line L2 (-70, 22) -> (-60, 22)
  line L3 (-70, 20) -> (-70, 22)
  line L4 (-60, 20) -> (-70, 20)
extrude "Extrude16" add sketch "Flat washer seat for sensor-drive shaft clamp" along normal blind 10
work_plane "WorkPlane17" AlongDistance 6.4 ExtraOffset 0
sketch "Radial screw onto printed shaft D flat" plane through (0, 6.4, 0) normal (0, 1, 0) x axis (1, 0, 0)
  circle C1 centre (0, -65) radius 1.7
extrude "Extrude17" cut sketch "Radial screw onto printed shaft D flat" along normal blind 15.7
work_plane "WorkPlane18" AlongDistance 15.2 ExtraOffset 0
sketch "M3 heatset pocket for rotor clamp" plane through (0, 15.2, 0) normal (0, 1, 0) x axis (1, 0, 0)
  circle C1 centre (0, -65) radius 2
work_plane "WorkPlane37" AlongDistance -24 ExtraOffset 0
sketch "Extend reaction block into free rail bay" plane through (-24, 0, 0) normal (1, 0, 0) x axis (0, 0, -1)
  line L1 (-38, -66) -> (-38, -74)
  line L2 (-59, -66) -> (-38, -66)
  line L3 (-59, -74) -> (-59, -66)
  line L4 (-38, -74) -> (-59, -74)
extrude "Extrude37" add sketch "Extend reaction block into free rail bay" along normal blind 48
work_plane "WorkPlane38" AlongDistance -24 ExtraOffset 0
sketch "Close mounting bore that crossed cup guide" plane through (-24, 0, 0) normal (1, 0, 0) x axis (0, 0, -1)
  circle C1 centre (-53.5, -54) radius 2.01
extrude "Extrude38" add sketch "Close mounting bore that crossed cup guide" along normal blind 8.7
work_plane "WorkPlane39" AlongDistance -24.1 ExtraOffset 0
sketch "Outer mounting row clear of guide" plane through (-24.1, 0, 0) normal (1, 0, 0) x axis (0, 0, -1)
  circle C1 centre (-53.5, -70) radius 2
extrude "Extrude39" cut sketch "Outer mounting row clear of guide" along normal blind 8.9
work_plane "WorkPlane40" AlongDistance 15.3 ExtraOffset 0
sketch "Close mounting bore that crossed cup guide (1)" plane through (15.3, 0, 0) normal (1, 0, 0) x axis (0, 0, -1)
  circle C1 centre (-53.5, -54) radius 2.01
extrude "Extrude40" add sketch "Close mounting bore that crossed cup guide (1)" along normal blind 8.7
work_plane "WorkPlane41" AlongDistance 15.2 ExtraOffset 0
sketch "Outer mounting row clear of guide (1)" plane through (15.2, 0, 0) normal (1, 0, 0) x axis (0, 0, -1)
  circle C1 centre (-53.5, -70) radius 2
extrude "Extrude41" cut sketch "Outer mounting row clear of guide (1)" along normal blind 8.9
work_plane "WorkPlane34" AlongDistance -36 ExtraOffset 0
sketch "Close former inner mounting hole" plane through (-36, 0, 0) normal (1, 0, 0) x axis (0, 0, -1)
  circle C1 centre (-53.5, -54) radius 1.71
extrude "Extrude34" add sketch "Close former inner mounting hole" along normal blind 12
work_plane "WorkPlane35" AlongDistance -36.1 ExtraOffset 0
sketch "Matched outer mounting row" plane through (-36.1, 0, 0) normal (1, 0, 0) x axis (0, 0, -1)
  circle C1 centre (-53.5, -70) radius 1.7
extrude "Extrude35" cut sketch "Matched outer mounting row" along normal blind 12.2
work_plane "WorkPlane33" AlongDistance 24 ExtraOffset 0
sketch "Close former inner mounting hole" plane through (24, 0, 0) normal (1, 0, 0) x axis (0, 0, -1)
  circle C1 centre (-53.5, -54) radius 1.71
extrude "Extrude33" add sketch "Close former inner mounting hole" along normal blind 12
work_plane "WorkPlane34" AlongDistance 23.9 ExtraOffset 0
sketch "Matched outer mounting row" plane through (23.9, 0, 0) normal (1, 0, 0) x axis (0, 0, -1)
  circle C1 centre (-53.5, -70) radius 1.7
extrude "Extrude34" cut sketch "Matched outer mounting row" along normal blind 12.2
work_plane "WorkPlane42" AlongDistance 37.9 ExtraOffset 0
sketch "Restore separate cup guide bore" plane through (0, 0, 37.9) normal (0, 0, 1) x axis (1, 0, 0)
  circle C1 centre (5, -55) radius 1.7
work_plane "WorkPlane43" AlongDistance 37.9 ExtraOffset 0
sketch "Restore separate cup guide bore (1)" plane through (0, 0, 37.9) normal (0, 0, 1) x axis (1, 0, 0)
  circle C1 centre (19, -55) radius 1.7
extrude "Extrude43" cut sketch "Restore separate cup guide bore (1)" along normal blind 21.2
work_plane "WorkPlane44" AlongDistance -24.1 ExtraOffset 0
sketch "Preserve cam envelope" plane through (-24.1, 0, 0) normal (1, 0, 0) x axis (0, 0, -1)
  circle C1 centre (-65, 0) radius 51
work_plane "WorkPlane36" AlongDistance -55 ExtraOffset 0
sketch "Close inaccessible rail head pocket" plane through (0, -55, 0) normal (0, 1, 0) x axis (1, 0, 0)
  circle C1 centre (-30, -45) radius 5.31
extrude "Extrude36" add sketch "Close inaccessible rail head pocket" along normal blind 12
work_plane "WorkPlane37" AlongDistance 43 ExtraOffset 0
sketch "Close inaccessible rail head pocket (1)" plane through (0, 43, 0) normal (0, 1, 0) x axis (1, 0, 0)
  circle C1 centre (-30, -45) radius 5.31
extrude "Extrude37" add sketch "Close inaccessible rail head pocket (1)" along normal blind 12
work_plane "WorkPlane38" AlongDistance -75 ExtraOffset 0
sketch "Close obsolete side rail bore" plane through (0, -75, 0) normal (0, 1, 0) x axis (1, 0, 0)
  circle C1 centre (-30, -45) radius 2.71
extrude "Extrude38" add sketch "Close obsolete side rail bore" along normal blind 20
work_plane "WorkPlane39" AlongDistance 55 ExtraOffset 0
sketch "Close obsolete side rail bore (1)" plane through (0, 55, 0) normal (0, 1, 0) x axis (1, 0, 0)
  circle C1 centre (-30, -45) radius 2.71
extrude "Extrude39" add sketch "Close obsolete side rail bore (1)" along normal blind 20
work_plane "WorkPlane40" AlongDistance -36 ExtraOffset 0
sketch "Top-access 2020 mounting flange" plane through (-36, 0, 0) normal (1, 0, 0) x axis (0, 0, -1)
  line L1 (-55, -70) -> (-55, -95)
  line L2 (-63, -70) -> (-55, -70)
  line L3 (-63, -95) -> (-63, -70)
  line L4 (-55, -95) -> (-63, -95)
extrude "Extrude40" add sketch "Top-access 2020 mounting flange" along normal blind 12
work_plane "WorkPlane41" AlongDistance -36 ExtraOffset 0
sketch "Mount root triangular reinforcement" plane through (-36, 0, 0) normal (1, 0, 0) x axis (0, 0, -1)
  line L1 (-56, -63) -> (-56, -70)
  line L2 (-63, -70) -> (-56, -63)
  line L3 (-56, -70) -> (-63, -70)
extrude "Extrude41" add sketch "Mount root triangular reinforcement" along normal blind 12
work_plane "WorkPlane42" AlongDistance 54.9 ExtraOffset 0
sketch "Vertical M5 rail mounting bore" plane through (0, 0, 54.9) normal (0, 0, 1) x axis (1, 0, 0)
  circle C1 centre (-30, -85) radius 2.7
extrude "Extrude42" cut sketch "Vertical M5 rail mounting bore" along normal blind 8.2
work_plane "WorkPlane43" AlongDistance -36 ExtraOffset 0
sketch "Top-access 2020 mounting flange (1)" plane through (-36, 0, 0) normal (1, 0, 0) x axis (0, 0, -1)
  line L1 (-55, 95) -> (-55, 70)
  line L2 (-63, 95) -> (-55, 95)
  line L3 (-63, 70) -> (-63, 95)
  line L4 (-55, 70) -> (-63, 70)
extrude "Extrude43" add sketch "Top-access 2020 mounting flange (1)" along normal blind 12
work_plane "WorkPlane44" AlongDistance -36 ExtraOffset 0
sketch "Mount root triangular reinforcement (1)" plane through (-36, 0, 0) normal (1, 0, 0) x axis (0, 0, -1)
  line L1 (-56, 70) -> (-56, 63)
  line L2 (-63, 70) -> (-56, 70)
  line L3 (-56, 63) -> (-63, 70)
extrude "Extrude44" add sketch "Mount root triangular reinforcement (1)" along normal blind 12
work_plane "WorkPlane45" AlongDistance 54.9 ExtraOffset 0
sketch "Vertical M5 rail mounting bore (1)" plane through (0, 0, 54.9) normal (0, 0, 1) x axis (1, 0, 0)
  circle C1 centre (-30, 85) radius 2.7
extrude "Extrude45" cut sketch "Vertical M5 rail mounting bore (1)" along normal blind 8.2
work_plane "WorkPlane46" AlongDistance -36 ExtraOffset 0
sketch "Close old M5 pivot clearance" plane through (-36, 0, 0) normal (1, 0, 0) x axis (0, 0, -1)
  circle C1 centre (-12, -35) radius 2.71
extrude "Extrude46" add sketch "Close old M5 pivot clearance" along normal blind 12
work_plane "WorkPlane47" AlongDistance -36.1 ExtraOffset 0
sketch "M3 follower pivot clearance" plane through (-36.1, 0, 0) normal (1, 0, 0) x axis (0, 0, -1)
  circle C1 centre (-12, -35) radius 1.7
extrude "Extrude47" cut sketch "M3 follower pivot clearance" along normal blind 12.2
work_plane "WorkPlane35" AlongDistance -55 ExtraOffset 0
sketch "Close inaccessible rail head pocket" plane through (0, -55, 0) normal (0, 1, 0) x axis (1, 0, 0)
  circle C1 centre (30, -45) radius 5.31
extrude "Extrude35" add sketch "Close inaccessible rail head pocket" along normal blind 12
work_plane "WorkPlane36" AlongDistance 43 ExtraOffset 0
sketch "Close inaccessible rail head pocket (1)" plane through (0, 43, 0) normal (0, 1, 0) x axis (1, 0, 0)
  circle C1 centre (30, -45) radius 5.31
extrude "Extrude36" add sketch "Close inaccessible rail head pocket (1)" along normal blind 12
work_plane "WorkPlane37" AlongDistance -75 ExtraOffset 0
sketch "Close obsolete side rail bore" plane through (0, -75, 0) normal (0, 1, 0) x axis (1, 0, 0)
  circle C1 centre (30, -45) radius 2.71
extrude "Extrude37" add sketch "Close obsolete side rail bore" along normal blind 20
work_plane "WorkPlane38" AlongDistance 55 ExtraOffset 0
sketch "Close obsolete side rail bore (1)" plane through (0, 55, 0) normal (0, 1, 0) x axis (1, 0, 0)
  circle C1 centre (30, -45) radius 2.71
extrude "Extrude38" add sketch "Close obsolete side rail bore (1)" along normal blind 20
work_plane "WorkPlane39" AlongDistance 24 ExtraOffset 0
sketch "Top-access 2020 mounting flange" plane through (24, 0, 0) normal (1, 0, 0) x axis (0, 0, -1)
  line L1 (-55, -70) -> (-55, -95)
  line L2 (-63, -70) -> (-55, -70)
  line L3 (-63, -95) -> (-63, -70)
  line L4 (-55, -95) -> (-63, -95)
extrude "Extrude39" add sketch "Top-access 2020 mounting flange" along normal blind 12
work_plane "WorkPlane40" AlongDistance 24 ExtraOffset 0
sketch "Mount root triangular reinforcement" plane through (24, 0, 0) normal (1, 0, 0) x axis (0, 0, -1)
  line L1 (-56, -63) -> (-56, -70)
  line L2 (-63, -70) -> (-56, -63)
  line L3 (-56, -70) -> (-63, -70)
extrude "Extrude40" add sketch "Mount root triangular reinforcement" along normal blind 12
work_plane "WorkPlane41" AlongDistance 54.9 ExtraOffset 0
sketch "Vertical M5 rail mounting bore" plane through (0, 0, 54.9) normal (0, 0, 1) x axis (1, 0, 0)
  circle C1 centre (30, -85) radius 2.7
extrude "Extrude41" cut sketch "Vertical M5 rail mounting bore" along normal blind 8.2
work_plane "WorkPlane42" AlongDistance 24 ExtraOffset 0
sketch "Top-access 2020 mounting flange (1)" plane through (24, 0, 0) normal (1, 0, 0) x axis (0, 0, -1)
  line L1 (-55, 95) -> (-55, 70)
  line L2 (-63, 95) -> (-55, 95)
  line L3 (-63, 70) -> (-63, 95)
  line L4 (-55, 70) -> (-63, 70)
extrude "Extrude42" add sketch "Top-access 2020 mounting flange (1)" along normal blind 12
work_plane "WorkPlane43" AlongDistance 24 ExtraOffset 0
sketch "Mount root triangular reinforcement (1)" plane through (24, 0, 0) normal (1, 0, 0) x axis (0, 0, -1)
  line L1 (-56, 70) -> (-56, 63)
  line L2 (-63, 70) -> (-56, 70)
  line L3 (-56, 63) -> (-63, 70)
extrude "Extrude43" add sketch "Mount root triangular reinforcement (1)" along normal blind 12
work_plane "WorkPlane44" AlongDistance 54.9 ExtraOffset 0
sketch "Vertical M5 rail mounting bore (1)" plane through (0, 0, 54.9) normal (0, 0, 1) x axis (1, 0, 0)
  circle C1 centre (30, 85) radius 2.7
extrude "Extrude44" cut sketch "Vertical M5 rail mounting bore (1)" along normal blind 8.2
work_plane "WorkPlane45" AlongDistance 24 ExtraOffset 0
sketch "Close old M5 pivot clearance" plane through (24, 0, 0) normal (1, 0, 0) x axis (0, 0, -1)
  circle C1 centre (-12, -35) radius 2.71
extrude "Extrude45" add sketch "Close old M5 pivot clearance" along normal blind 12
work_plane "WorkPlane46" AlongDistance 23.9 ExtraOffset 0
sketch "M3 follower pivot clearance" plane through (23.9, 0, 0) normal (1, 0, 0) x axis (0, 0, -1)
  circle C1 centre (-12, -35) radius 1.7
extrude "Extrude46" cut sketch "M3 follower pivot clearance" along normal blind 12.2
work_plane "WorkPlane47" AlongDistance 23.9 ExtraOffset 0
